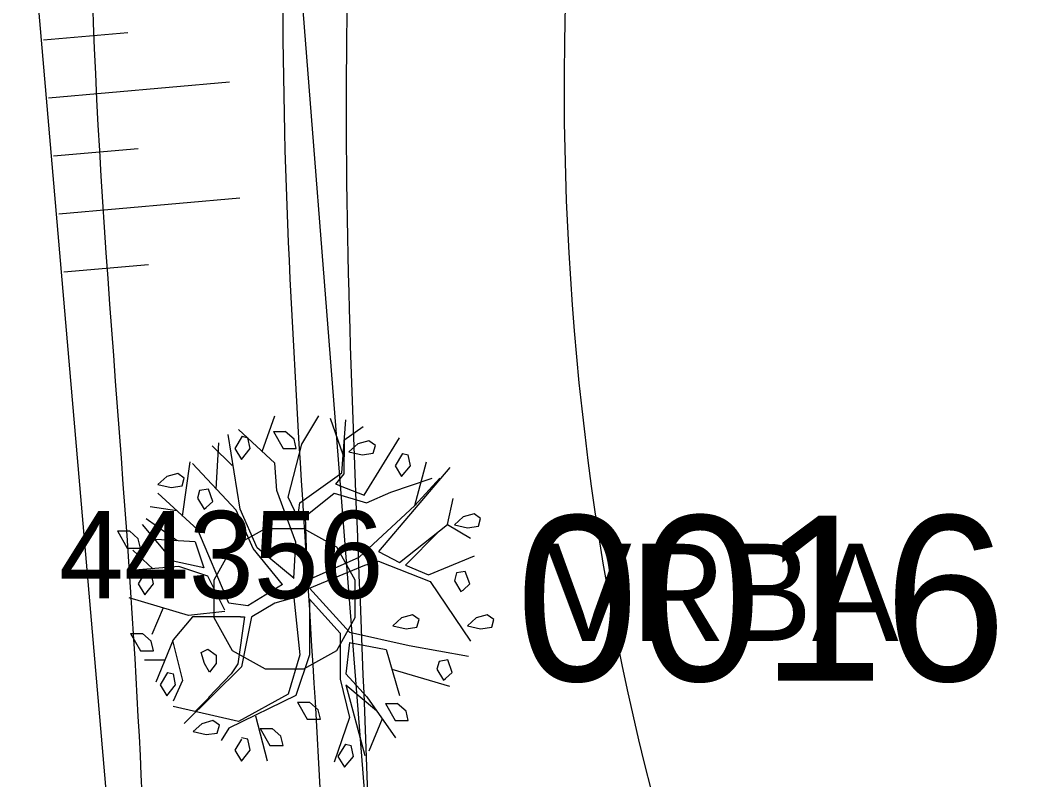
# Model space of a CAD drawing. Extents: x -598521 to -597689, y -1074676 to -1074150.
# Drawn here: x -598485.7 to -598480.53, y -1074201.09 to -1074197.17 of the extents above; entities that cross this region are included whole.
import ezdxf

# ---------------------------------------------------------------- set-up
doc = ezdxf.new("R2010")
doc.units = 0
for name, color, linetype in [('Vrstva 1', 7, 'Continuous'), ('Vrstva 10', 7, 'Continuous'), ('Vrstva 12', 7, 'Continuous'), ('Vrstva 2', 7, 'Continuous'), ('Vrstva 3', 7, 'Continuous')]:
    doc.layers.add(name, color=color, linetype=linetype)

msp = doc.modelspace()

# ---------------------------------------------------------------- linework, layer by layer
at = {"layer": 'Vrstva 1'}
msp.add_line((-598484.36, -1074200.154), (-598484.31, -1074200.154), dxfattribs=at)
msp.add_lwpolyline([(-598484.24, -1074199.794), (-598484.07, -1074199.889), (-598483.975, -1074200.059), (-598483.975, -1074200.254), (-598484.07, -1074200.424), (-598484.24, -1074200.519), (-598484.435, -1074200.519), (-598484.605, -1074200.424), (-598484.7, -1074200.254), (-598484.7, -1074200.059), (-598484.605, -1074199.889), (-598484.435, -1074199.794)], close=True, dxfattribs=at)
at = {"layer": 'Vrstva 10'}
for p, q in [((-598485.58, -1074197.2766), (-598485.1445, -1074197.2381)), ((-598485.5536, -1074197.5754), (-598484.6201, -1074197.4929)), ((-598485.5272, -1074197.8743), (-598485.0917, -1074197.8358)), ((-598485.5008, -1074198.1731), (-598484.5673, -1074198.0906)), ((-598485.4744, -1074198.4719), (-598485.0389, -1074198.4335)), ((-598484.4527, -1074199.3979), (-598484.3872, -1074199.2134)), ((-598484.2487, -1074199.3604), (-598484.1602, -1074199.2134)), ((-598484.0347, -1074199.4144), (-598484.1007, -1074199.2274)), ((-598484.0412, -1074199.5074), (-598484.0212, -1074199.2344)), ((-598484.3872, -1074199.4584), (-598484.5752, -1074199.2834)), ((-598484.3947, -1074199.2944), (-598484.3447, -1074199.3824)), ((-598484.3947, -1074199.2944), (-598484.3337, -1074199.2944)), ((-598484.2882, -1074199.3344), (-598484.3337, -1074199.2944)), ((-598484.0312, -1074199.3394), (-598483.9322, -1074199.2694)), ((-598484.6897, -1074199.5909), (-598484.6762, -1074199.3534)), ((-598484.5667, -1074199.6954), (-598484.6282, -1074199.3104)), ((-598484.5557, -1074199.3194), (-598484.5937, -1074199.3824)), ((-598484.5557, -1074199.3194), (-598484.5257, -1074199.3264)), ((-598484.5147, -1074199.3824), (-598484.5257, -1074199.3264)), ((-598484.2767, -1074199.3824), (-598484.2882, -1074199.3344)), ((-598484.0297, -1074199.5124), (-598484.0277, -1074199.3404)), ((-598483.9602, -1074199.3584), (-598484.0052, -1074199.3989)), ((-598483.9032, -1074199.3424), (-598483.9602, -1074199.3584)), ((-598483.9262, -1074199.6229), (-598483.7452, -1074199.3264)), ((-598483.8692, -1074199.3664), (-598483.9032, -1074199.3424)), ((-598484.6077, -1074199.4694), (-598484.7097, -1074199.3679)), ((-598484.5937, -1074199.3824), (-598484.5597, -1074199.4384)), ((-598484.5597, -1074199.4384), (-598484.5147, -1074199.3824)), ((-598484.3447, -1074199.3824), (-598484.2767, -1074199.3824)), ((-598484.3182, -1074199.6334), (-598484.2487, -1074199.3604)), ((-598484.0052, -1074199.3989), (-598483.9377, -1074199.4144)), ((-598483.9377, -1074199.4144), (-598483.8812, -1074199.4064)), ((-598483.8812, -1074199.4064), (-598483.8692, -1074199.3664)), ((-598483.7297, -1074199.4079), (-598483.7677, -1074199.4709)), ((-598483.7297, -1074199.4079), (-598483.6997, -1074199.4144)), ((-598484.8622, -1074199.7314), (-598484.8227, -1074199.4514)), ((-598484.5872, -1074199.7004), (-598484.8117, -1074199.4599)), ((-598484.3772, -1074199.5984), (-598484.3872, -1074199.4584)), ((-598483.6887, -1074199.4709), (-598483.6997, -1074199.4144)), ((-598483.6657, -1074199.6754), (-598483.6062, -1074199.4514)), ((-598484.8877, -1074199.5109), (-598484.9442, -1074199.5264)), ((-598484.8542, -1074199.5349), (-598484.8877, -1074199.5109)), ((-598484.2587, -1074199.6614), (-598484.0412, -1074199.5074)), ((-598484.0722, -1074199.5654), (-598484.0297, -1074199.5124)), ((-598483.4857, -1074199.4794), (-598483.8532, -1074199.9134)), ((-598483.7677, -1074199.4709), (-598483.7337, -1074199.5264)), ((-598483.7337, -1074199.5264), (-598483.6887, -1074199.4709)), ((-598484.9442, -1074199.5264), (-598484.9897, -1074199.5669)), ((-598484.9897, -1074199.5669), (-598484.9217, -1074199.5829)), ((-598484.8652, -1074199.5749), (-598484.8542, -1074199.5349)), ((-598484.0517, -1074199.5744), (-598484.0722, -1074199.5654)), ((-598483.7902, -1074199.6069), (-598483.5757, -1074199.5349)), ((-598483.6657, -1074199.6754), (-598483.5367, -1074199.5354)), ((-598484.7832, -1074199.8014), (-598484.9902, -1074199.6124)), ((-598484.9217, -1074199.5829), (-598484.8652, -1074199.5749)), ((-598484.7747, -1074199.5989), (-598484.7857, -1074199.6389)), ((-598484.7297, -1074199.5909), (-598484.7747, -1074199.5989)), ((-598484.7067, -1074199.6549), (-598484.7297, -1074199.5909)), ((-598484.2787, -1074199.8644), (-598484.3772, -1074199.5984)), ((-598484.2292, -1074199.7314), (-598484.0807, -1074199.6124)), ((-598484.0807, -1074199.6124), (-598483.9147, -1074199.6629)), ((-598484.0502, -1074199.5749), (-598483.9262, -1074199.6229)), ((-598483.9147, -1074199.6629), (-598483.7902, -1074199.6069)), ((-598484.7857, -1074199.6389), (-598484.7522, -1074199.6949)), ((-598484.7407, -1074199.6869), (-598484.7067, -1074199.6549)), ((-598484.2687, -1074199.7384), (-598484.3182, -1074199.6334)), ((-598484.2687, -1074199.7384), (-598484.2587, -1074199.6614)), ((-598483.4972, -1074199.7734), (-598483.4677, -1074199.6404)), ((-598484.8917, -1074199.7034), (-598485.0297, -1074199.6824)), ((-598484.7522, -1074199.6949), (-598484.7407, -1074199.6869)), ((-598484.4987, -1074199.8979), (-598484.5872, -1074199.7004)), ((-598484.4782, -1074199.8934), (-598484.5667, -1074199.6954)), ((-598483.9522, -1074199.9414), (-598483.6657, -1074199.6754)), ((-598483.3602, -1074199.7189), (-598483.4167, -1074199.7349)), ((-598483.3267, -1074199.7429), (-598483.3602, -1074199.7189)), ((-598484.9112, -1074199.9624), (-598485.0697, -1074199.7734)), ((-598484.8912, -1074199.8579), (-598485.0497, -1074199.7454)), ((-598484.2192, -1074200.0604), (-598484.2292, -1074199.7314)), ((-598483.7447, -1074199.9694), (-598483.4972, -1074199.7734)), ((-598483.4972, -1074199.7734), (-598483.3787, -1074199.8434)), ((-598483.4167, -1074199.7349), (-598483.4622, -1074199.7749)), ((-598483.3377, -1074199.7829), (-598483.3267, -1074199.7429)), ((-598485.1977, -1074199.8069), (-598485.1482, -1074199.8954)), ((-598485.1977, -1074199.8069), (-598485.1367, -1074199.8069)), ((-598485.0912, -1074199.8474), (-598485.1367, -1074199.8069)), ((-598484.6247, -1074200.1794), (-598484.7832, -1074199.8014)), ((-598483.7147, -1074199.9834), (-598483.5447, -1074199.8114)), ((-598483.4622, -1074199.7749), (-598483.3942, -1074199.7909)), ((-598483.3942, -1074199.7909), (-598483.3377, -1074199.7829)), ((-598485.0802, -1074199.8954), (-598485.0912, -1074199.8474)), ((-598484.7982, -1074199.8639), (-598485.0007, -1074199.8504)), ((-598484.7982, -1074199.8639), (-598484.7532, -1074199.9974)), ((-598484.2887, -1074200.0514), (-598484.2787, -1074199.8644)), ((-598485.1482, -1074199.8954), (-598485.0802, -1074199.8954)), ((-598485.0152, -1074200.0019), (-598485.1192, -1074199.9064)), ((-598484.3472, -1074200.0829), (-598484.4987, -1074199.8979)), ((-598484.2877, -1074200.0524), (-598484.4782, -1074199.8934)), ((-598483.8532, -1074199.9134), (-598483.7447, -1074199.9694)), ((-598484.7532, -1074199.9974), (-598484.9112, -1074199.9624)), ((-598484.2192, -1074200.0604), (-598483.9522, -1074199.9414)), ((-598483.9227, -1074199.9834), (-598483.8532, -1074199.9624)), ((-598483.8532, -1074199.9624), (-598483.5867, -1074200.0674)), ((-598483.5962, -1074200.0324), (-598483.3587, -1074199.9344)), ((-598484.8817, -1074199.9904), (-598485.1287, -1074200.0114)), ((-598485.0532, -1074200.0164), (-598485.0912, -1074200.0794)), ((-598485.0532, -1074200.0164), (-598485.0237, -1074200.0234)), ((-598485.0122, -1074200.0794), (-598485.0237, -1074200.0234)), ((-598484.7332, -1074200.0394), (-598484.8817, -1074199.9904)), ((-598484.2092, -1074200.1024), (-598483.9227, -1074199.9834)), ((-598483.7147, -1074199.9834), (-598483.5962, -1074200.0324)), ((-598483.4507, -1074200.0234), (-598483.4622, -1074200.0634)), ((-598483.4057, -1074200.0154), (-598483.4507, -1074200.0234)), ((-598483.3832, -1074200.0794), (-598483.4057, -1074200.0154)), ((-598485.0912, -1074200.0794), (-598485.0577, -1074200.1354)), ((-598485.0577, -1074200.1354), (-598485.0122, -1074200.0794)), ((-598484.6447, -1074200.2144), (-598484.7332, -1074200.0394)), ((-598484.3472, -1074200.0829), (-598484.5257, -1074200.1934)), ((-598483.5867, -1074200.0674), (-598483.3787, -1074200.3754)), ((-598483.4622, -1074200.0634), (-598483.4282, -1074200.1194)), ((-598483.4167, -1074200.1114), (-598483.3832, -1074200.0794)), ((-598484.2732, -1074200.1009), (-598484.2812, -1074200.1009)), ((-598484.2732, -1074200.1009), (-598484.2732, -1074200.0934)), ((-598484.2732, -1074200.1009), (-598484.2732, -1074200.1084)), ((-598484.2732, -1074200.1009), (-598484.2657, -1074200.1009)), ((-598484.0027, -1074200.3284), (-598484.2092, -1074200.1024)), ((-598483.4282, -1074200.1194), (-598483.4167, -1074200.1114)), ((-598484.8322, -1074200.2424), (-598485.1387, -1074200.1514)), ((-598484.5257, -1074200.1934), (-598484.6247, -1074200.1794)), ((-598484.3872, -1074200.1794), (-598484.5062, -1074200.2494)), ((-598484.2887, -1074200.1514), (-598484.3872, -1074200.1794)), ((-598484.2887, -1074200.1514), (-598484.2587, -1074200.4454)), ((-598484.2092, -1074200.1584), (-598484.2092, -1074200.4454)), ((-598484.2092, -1074200.1584), (-598484.0512, -1074200.3334)), ((-598484.9622, -1074200.2039), (-598485.0202, -1074200.3404)), ((-598484.6447, -1074200.2214), (-598484.8322, -1074200.2424)), ((-598483.6772, -1074200.2394), (-598483.7337, -1074200.2554)), ((-598483.6432, -1074200.2634), (-598483.6772, -1074200.2394)), ((-598483.2927, -1074200.2394), (-598483.3492, -1074200.2554)), ((-598483.2587, -1074200.2634), (-598483.2927, -1074200.2394)), ((-598484.8122, -1074200.2494), (-598484.9112, -1074200.3684)), ((-598484.5647, -1074200.2494), (-598484.8122, -1074200.2494)), ((-598484.5437, -1074200.2489), (-598484.5777, -1074200.4914)), ((-598484.5647, -1074200.2489), (-598484.5437, -1074200.2489)), ((-598484.5067, -1074200.2489), (-598484.5597, -1074200.5079)), ((-598484.5067, -1074200.2494), (-598484.5062, -1074200.2494)), ((-598483.7337, -1074200.2554), (-598483.7792, -1074200.2954)), ((-598483.6547, -1074200.3034), (-598483.6432, -1074200.2634)), ((-598483.3492, -1074200.2554), (-598483.3942, -1074200.2954)), ((-598483.2697, -1074200.3034), (-598483.2587, -1074200.2634)), ((-598485.1302, -1074200.3359), (-598485.0687, -1074200.3359)), ((-598485.1302, -1074200.3359), (-598485.0802, -1074200.4239)), ((-598485.0237, -1074200.3754), (-598485.0687, -1074200.3359)), ((-598484.0512, -1074200.3334), (-598484.0512, -1074200.5714)), ((-598484.0027, -1074200.3284), (-598483.6952, -1074200.3964)), ((-598483.7792, -1074200.2954), (-598483.7112, -1074200.3119)), ((-598483.7112, -1074200.3119), (-598483.6547, -1074200.3034)), ((-598483.3942, -1074200.2954), (-598483.3267, -1074200.3119)), ((-598483.3267, -1074200.3119), (-598483.2697, -1074200.3034)), ((-598485.0122, -1074200.4239), (-598485.0237, -1074200.3754)), ((-598484.9112, -1074200.3684), (-598485.0007, -1074200.5854)), ((-598484.9142, -1074200.3719), (-598484.8622, -1074200.5784)), ((-598484.0017, -1074200.3824), (-598484.0212, -1074200.5434)), ((-598484.0017, -1074200.3824), (-598483.8137, -1074200.4174)), ((-598485.0802, -1074200.4239), (-598485.0122, -1074200.4239)), ((-598484.7677, -1074200.4339), (-598484.7327, -1074200.4154)), ((-598484.7502, -1074200.4904), (-598484.7677, -1074200.4339)), ((-598484.7327, -1074200.4154), (-598484.6887, -1074200.4464)), ((-598484.6887, -1074200.4464), (-598484.6887, -1074200.4904)), ((-598484.2587, -1074200.4454), (-598484.3182, -1074200.6484)), ((-598484.2092, -1074200.4454), (-598484.2787, -1074200.6554)), ((-598483.8137, -1074200.4174), (-598483.7447, -1074200.6554)), ((-598483.6952, -1074200.3964), (-598483.3887, -1074200.4524)), ((-598484.9542, -1074200.4734), (-598485.0597, -1074200.4734)), ((-598484.7237, -1074200.5339), (-598484.7502, -1074200.4904)), ((-598484.6887, -1074200.4904), (-598484.7237, -1074200.5339)), ((-598484.5777, -1074200.4914), (-598484.6122, -1074200.5434)), ((-598483.5412, -1074200.4799), (-598483.5527, -1074200.5199)), ((-598483.4962, -1074200.4719), (-598483.5412, -1074200.4799)), ((-598483.4737, -1074200.5359), (-598483.4962, -1074200.4719)), ((-598484.9402, -1074200.5369), (-598484.9787, -1074200.6004)), ((-598484.9402, -1074200.5369), (-598484.9102, -1074200.5439)), ((-598484.8992, -1074200.6004), (-598484.9102, -1074200.5439)), ((-598484.5597, -1074200.5079), (-598484.8542, -1074200.7989)), ((-598484.6122, -1074200.5434), (-598484.7282, -1074200.6649)), ((-598484.0212, -1074200.5434), (-598483.9127, -1074200.6624)), ((-598483.7842, -1074200.5199), (-598483.4877, -1074200.6064)), ((-598483.5527, -1074200.5199), (-598483.5187, -1074200.5759)), ((-598483.5077, -1074200.5679), (-598483.4737, -1074200.5359)), ((-598484.9787, -1074200.6004), (-598484.9442, -1074200.6559)), ((-598484.9442, -1074200.6559), (-598484.8992, -1074200.6004)), ((-598484.8622, -1074200.5784), (-598484.9112, -1074200.6834)), ((-598484.0512, -1074200.5714), (-598484.0017, -1074200.7674)), ((-598484.0212, -1074200.5994), (-598483.9227, -1074200.9634)), ((-598484.0212, -1074200.5994), (-598483.8637, -1074200.7319)), ((-598483.5187, -1074200.5759), (-598483.5077, -1074200.5679)), ((-598484.3182, -1074200.6484), (-598484.5752, -1074200.7884)), ((-598484.7247, -1074200.6634), (-598484.7952, -1074200.7364)), ((-598484.2787, -1074200.6554), (-598484.6247, -1074200.8234)), ((-598484.2702, -1074200.6884), (-598484.2202, -1074200.7764)), ((-598484.2702, -1074200.6884), (-598484.2092, -1074200.6884)), ((-598484.1637, -1074200.7279), (-598484.2092, -1074200.6884)), ((-598483.9127, -1074200.6624), (-598483.7647, -1074200.8724)), ((-598483.8172, -1074200.6964), (-598483.7677, -1074200.7844)), ((-598483.8172, -1074200.6964), (-598483.7567, -1074200.6964)), ((-598483.7112, -1074200.7359), (-598483.7567, -1074200.6964)), ((-598484.5752, -1074200.7884), (-598484.9112, -1074200.7114)), ((-598484.1522, -1074200.7764), (-598484.1637, -1074200.7279)), ((-598483.6997, -1074200.7844), (-598483.7112, -1074200.7359)), ((-598484.7632, -1074200.8004), (-598484.8087, -1074200.8404)), ((-598484.7067, -1074200.7844), (-598484.7632, -1074200.8004)), ((-598484.6732, -1074200.8084), (-598484.7067, -1074200.7844)), ((-598484.6842, -1074200.8484), (-598484.6732, -1074200.8084)), ((-598484.4862, -1074200.7604), (-598484.4267, -1074200.9914)), ((-598484.2202, -1074200.7764), (-598484.1522, -1074200.7764)), ((-598484.0017, -1074200.7674), (-598484.0807, -1074200.9984)), ((-598483.8337, -1074200.7744), (-598483.9027, -1074200.9424)), ((-598483.7677, -1074200.7844), (-598483.6997, -1074200.7844)), ((-598484.8087, -1074200.8404), (-598484.7407, -1074200.8564)), ((-598484.7407, -1074200.8564), (-598484.6842, -1074200.8484)), ((-598484.6247, -1074200.8234), (-598484.6642, -1074200.8864)), ((-598484.4627, -1074200.8244), (-598484.4012, -1074200.8244)), ((-598484.4627, -1074200.8244), (-598484.4127, -1074200.9124)), ((-598484.3557, -1074200.8644), (-598484.4012, -1074200.8244)), ((-598484.5597, -1074200.8804), (-598484.5937, -1074200.9364)), ((-598484.5257, -1074200.8804), (-598484.5597, -1074200.8724)), ((-598484.5147, -1074200.9364), (-598484.5257, -1074200.8804)), ((-598484.3447, -1074200.9124), (-598484.3557, -1074200.8644)), ((-598484.0237, -1074200.9054), (-598484.0622, -1074200.9684)), ((-598484.0237, -1074200.9054), (-598483.9942, -1074200.9124)), ((-598484.5937, -1074200.9364), (-598484.5597, -1074200.9924)), ((-598484.5597, -1074200.9924), (-598484.5147, -1074200.9364)), ((-598484.4127, -1074200.9124), (-598484.3447, -1074200.9124)), ((-598483.9827, -1074200.9684), (-598483.9942, -1074200.9124)), ((-598484.0622, -1074200.9684), (-598484.0277, -1074201.0244)), ((-598484.0277, -1074201.0244), (-598483.9827, -1074200.9684))]:
    msp.add_line(p, q, dxfattribs=at)
for points in [[(-598473.1747, -1074171.1286), (-598470.76, -1074168.97), (-598466.97, -1074166.72), (-598463.6963, -1074165.8585), (-598453.0957, -1074164.7101), (-598446.41, -1074166.04), (-598435.0791, -1074171.7728), (-598423.335, -1074177.929), (-598417.6588, -1074181.967), (-598421.5192, -1074188.7867), (-598425.5298, -1074192.9474), (-598427.582, -1074193.806), (-598433.5332, -1074199.4315), (-598451.6779, -1074206.4632), (-598460.2114, -1074206.9049), (-598466.8897, -1074208.495), (-598478.9037, -1074213.9366), (-598483.5459, -1074205.9442), (-598484.31, -1074196.25), (-598482.5035, -1074189.5221), (-598479.9329, -1074184.3455), (-598477.96, -1074180.01), (-598476.52, -1074177.56)], [(-598476.61, -1074175.53), (-598476.74, -1074177.23), (-598478.1523, -1074179.8601), (-598480.08, -1074184.11), (-598482.8298, -1074189.4139), (-598485.7, -1074196.02), (-598484.7777, -1074206.7238), (-598481.095, -1074214.938)]]:
    msp.add_lwpolyline(points, dxfattribs=at)
at = {"layer": 'Vrstva 12'}
for points in [[(-598477.8556, -1074175.904), (-598479.1078, -1074177.8729), (-598481.8726, -1074181.1437), (-598482.7141, -1074182.6203), (-598484.1249, -1074188.1901), (-598485.3348, -1074196.141), (-598485.1135, -1074200.3642), (-598484.5003, -1074206.6546), (-598482.5365, -1074211.2544), (-598480.2074, -1074214.488), (-598467.7934, -1074210.2137), (-598459.7245, -1074208.727), (-598453.744, -1074207.7606), (-598434.0451, -1074202.2598), (-598426.9437, -1074195.6068), (-598420.2001, -1074189.3976), (-598414.7551, -1074180.1636), (-598419.1594, -1074177.7291), (-598424.716, -1074175.6663), (-598432.261, -1074171.9495), (-598446.2733, -1074165.3337), (-598449.2839, -1074163.0664), (-598455.0784, -1074161.4547), (-598458.6047, -1074161.8006), (-598464.2812, -1074162.7184), (-598468.1115, -1074164.5618), (-598472.2785, -1074167.7063), (-598475.1383, -1074168.2051), (-598476.2523, -1074168.9159), (-598476.9776, -1074169.714), (-598477.6095, -1074175.2054), (-598477.8556, -1074175.904)], [(-598473.7888, -1074172.0394), (-598475.746, -1074175.8952), (-598480.6732, -1074186.045), (-598482.6711, -1074189.5445), (-598484.328, -1074196.2355), (-598484.11, -1074202.3062), (-598483.7681, -1074206.3141), (-598481.2248, -1074209.9404), (-598467.3573, -1074209.7347), (-598459.946, -1074208.1465), (-598451.7203, -1074206.1716), (-598433.8843, -1074198.9435), (-598427.582, -1074193.806), (-598421.589, -1074188.753), (-598417.6645, -1074181.613), (-598423.3772, -1074177.4754), (-598435.6533, -1074170.8396), (-598446.2268, -1074166.1248), (-598452.8538, -1074164.1253), (-598463.5233, -1074165.0858), (-598467.1, -1074166.52), (-598468.2906, -1074167.2623), (-598470.6829, -1074168.7005), (-598473.2194, -1074171.071)], [(-598473.7888, -1074172.0394), (-598475.746, -1074175.8952), (-598480.6732, -1074186.045), (-598482.6711, -1074189.5445), (-598484.328, -1074196.2355), (-598484.11, -1074202.3062), (-598483.7681, -1074206.3141), (-598481.2248, -1074209.9404), (-598467.3573, -1074209.7347), (-598459.946, -1074208.1465), (-598451.7203, -1074206.1716), (-598433.8843, -1074198.9435), (-598427.582, -1074193.806), (-598421.589, -1074188.753), (-598417.6645, -1074181.613), (-598423.3772, -1074177.4754), (-598435.6533, -1074170.8396), (-598446.2268, -1074166.1248), (-598452.8538, -1074164.1253), (-598463.5233, -1074165.0858), (-598467.1, -1074166.52), (-598468.2906, -1074167.2623), (-598470.6829, -1074168.7005), (-598473.2194, -1074171.071)], [(-598473.4477, -1074172.2328), (-598475.5803, -1074175.9222), (-598480.4655, -1074186.1252), (-598482.4005, -1074189.7295), (-598483.9812, -1074196.2295), (-598483.8858, -1074202.2525), (-598483.5459, -1074205.9442), (-598480.979, -1074209.1613), (-598475.1374, -1074210.0743), (-598467.0431, -1074208.9296), (-598460.0568, -1074207.6589), (-598451.8734, -1074205.6941), (-598431.7771, -1074196.4611), (-598429.1063, -1074194.1991), (-598419.8673, -1074184.7966), (-598419.8742, -1074181.8158), (-598423.6897, -1074178.1638), (-598435.5722, -1074171.1597), (-598446.4015, -1074166.5943), (-598452.7964, -1074164.4144), (-598463.3503, -1074165.3956), (-598466.975, -1074166.9354), (-598468.1128, -1074167.5827), (-598470.5929, -1074168.9794), (-598472.889, -1074171.3607)], [(-598473.7761, -1074172.0572), (-598475.7867, -1074175.8047), (-598476.6367, -1074177.2466), (-598477.7617, -1074179.2852), (-598478.7593, -1074181.5122), (-598479.981, -1074184.1107), (-598480.826, -1074187.6229), (-598482.8722, -1074196.6443), (-598480.8844, -1074204.4469), (-598462.2993, -1074205.951), (-598457.6214, -1074205.2443), (-598448.6, -1074200.2357), (-598431.1353, -1074190.0523), (-598425.671, -1074182.3452), (-598436.6403, -1074172.4362), (-598453.1707, -1074165.1777), (-598463.8596, -1074166.401), (-598467.0505, -1074166.6304), (-598468.6224, -1074167.548), (-598470.0019, -1074168.3687), (-598470.7965, -1074168.8969), (-598473.2009, -1074171.085)]]:
    msp.add_spline(points, degree=3, dxfattribs=at)

# ---------------------------------------------------------------- texts
at = {"layer": 'Vrstva 10'}
msp.add_text('VRBA', height=0.5, dxfattribs=at).set_placement((-598482.9939, -1074200.3733))
at = {"layer": 'Vrstva 2'}
msp.add_text('0016', height=0.85, dxfattribs=at).set_placement((-598483.145, -1074200.579))
at = {"layer": 'Vrstva 3'}
msp.add_text('44356', height=0.45, dxfattribs=at).set_placement((-598485.5, -1074200.154))

doc.saveas('drawing.dxf')
